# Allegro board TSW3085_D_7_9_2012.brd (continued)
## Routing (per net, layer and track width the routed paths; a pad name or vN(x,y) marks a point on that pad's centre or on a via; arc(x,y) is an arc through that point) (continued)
DA4N: length 53.3
  TOP w0.127: U1.A22 38.13,61.9
  TOP w0.152: 38.13,61.9 37.59,61.36 37.59,59.22 36.32,57.95 24.68,57.95 24.39,57.66 24.11,57.66 23.81,57.95 23.54,57.95 23.24,57.66 22.96,57.66 22.67,57.95 22.18,57.95 21.56,57.33 21.17,57.33 20.89,57.6 20.89,58.69 20.78,58.8 20.62,58.8 20.51,58.69 20.51,57.6 20.24,57.33 19.85,57.33 19.57,57.6 19.57,58.69 19.46,58.8 19.3,58.8 19.19,58.69 19.19,57.6 18.92,57.33 18.53,57.33 18.25,57.6 18.25,58.69 18.14,58.8 17.98,58.8 17.87,58.69 17.87,57.6 17.6,57.33 17.21,57.33 16.93,57.6 16.93,58.69 16.82,58.8 16.66,58.8 16.55,58.69 16.55,57.6 16.27,57.33 15.88,57.33 15.61,57.6 15.61,58.69 15.5,58.8 15.34,58.8 15.23,58.69 15.23,57.6 14.95,57.33 14.56,57.33 14.29,57.6 14.29,58.69 14.18,58.8 14.02,58.8 13.91,58.69 13.91,57.6 13.63,57.33 13.24,57.33 12.53,58.04 11.77,58.04 10.68,56.95 9.03,56.95 8.6,56.52 7.74,56.52 v1(7.29,56.06)
  BOTTOM w0.152: J13.141 6.13,55.98 6.24,56.09 6.39,56.09 6.67,56.36 6.99,56.36 v1(7.29,56.06)
DA4P: length 53.4
  TOP w0.127: 37.91,62.07 38.03,62.2 U1.B20
  TOP w0.152: v1(7.29,56.94) 7.44,56.79 8.48,56.79 8.92,57.23 10.57,57.23 11.66,58.32 12.65,58.32 13.36,57.61 13.52,57.61 13.63,57.72 13.63,58.81 13.9,59.08 14.29,59.08 14.57,58.81 14.57,57.72 14.68,57.61 14.84,57.61 14.95,57.72 14.95,58.81 15.22,59.08 15.61,59.08 15.89,58.81 15.89,57.72 16,57.61 16.16,57.61 16.27,57.72 16.27,58.81 16.55,59.08 16.93,59.08 17.21,58.81 17.21,57.72 17.32,57.61 17.48,57.61 17.59,57.72 17.59,58.81 17.87,59.08 18.26,59.08 18.53,58.81 18.53,57.72 18.64,57.61 18.8,57.61 18.91,57.72 18.91,58.81 19.19,59.08 19.58,59.08 19.85,58.81 19.85,57.72 19.96,57.61 20.12,57.61 20.23,57.72 20.23,58.81 20.51,59.08 20.9,59.08 21.17,58.81 21.17,57.72 21.28,57.61 21.44,57.61 22.07,58.23 36.21,58.23 37.31,59.34 37.31,61.48 37.91,62.07
  BOTTOM w0.152: J13.139 6.13,56.48 6.24,56.37 6.28,56.37 6.55,56.64 6.99,56.64 v1(7.29,56.94)
DA5N: length 53.3
  TOP w0.127: U1.A21 37.71,62.5
  TOP w0.152: v1(7.15,57.74) 7.4,57.99 7.99,57.99 8.57,58.57 10.87,58.57 12.14,59.84 21.66,59.84 21.81,59.69 22.09,59.69 22.24,59.84 22.52,59.84 22.67,59.69 22.95,59.69 23.11,59.84 23.39,59.84 23.54,59.69 23.82,59.69 23.97,59.84 24.36,59.84 25.3,58.9 26.64,58.9 27.39,59.65 27.39,60.65 27.5,60.76 27.66,60.76 27.77,60.65 27.77,59.2 28.05,58.93 28.44,58.93 28.71,59.2 28.71,60.65 28.82,60.76 28.98,60.76 29.09,60.65 29.09,59.2 29.37,58.93 29.76,58.93 30.03,59.2 30.03,60.65 30.14,60.76 30.3,60.76 30.41,60.65 30.41,59.2 30.69,58.93 31.08,58.93 31.35,59.2 31.35,60.65 31.46,60.76 31.62,60.76 31.73,60.65 31.73,59.2 32.01,58.93 32.4,58.93 32.67,59.2 32.67,60.65 32.79,60.76 32.94,60.76 33.05,60.65 33.05,59.2 33.33,58.93 33.72,58.93 34.08,59.28 34.08,60.34 34.82,61.09 36.3,61.09 37.71,62.5
  BOTTOM w0.152: v1(7.15,57.74) 6.85,58.04 6.55,58.04 6.39,57.89 6.39,57.74 6.13,57.48 J13.135
DA5P: length 53.4
  TOP w0.127: 37.74,62.78 37.76,62.8 U1.B19
  TOP w0.152: v1(7.15,58.62) 7.51,58.27 7.87,58.27 8.46,58.85 10.76,58.85 12.03,60.12 24.47,60.12 25.41,59.18 26.53,59.18 27.11,59.76 27.11,60.76 27.39,61.04 27.78,61.04 28.05,60.76 28.05,59.32 28.16,59.21 28.32,59.21 28.43,59.32 28.43,60.76 28.71,61.04 29.1,61.04 29.37,60.76 29.37,59.32 29.48,59.21 29.64,59.21 29.75,59.32 29.75,60.76 30.03,61.04 30.42,61.04 30.69,60.76 30.69,59.32 30.8,59.21 30.96,59.21 31.07,59.32 31.07,60.76 31.35,61.04 31.74,61.04 32.01,60.76 32.01,59.32 32.12,59.21 32.28,59.21 32.39,59.32 32.39,60.76 32.67,61.04 33.06,61.04 33.33,60.76 33.33,59.32 33.45,59.21 33.6,59.21 33.8,59.4 33.8,60.46 34.71,61.37 36.19,61.37 37.6,62.78 37.74,62.78
  BOTTOM w0.152: v1(7.15,58.62) 6.85,58.32 6.43,58.32 6.12,58 6.12,57.98 J13.133
DA6N: length 53.2
  TOP w0.127: U1.A20 38.05,63.1 38.04,63.11
  TOP w0.152: 38.04,63.11 37.22,63.11 36.35,62.23 34.87,62.23 34.38,61.75 24.91,61.75 24.77,61.61 24.77,61.01 24.46,60.71 24.03,60.71 23.72,61.01 23.72,62.08 23.57,62.23 23.37,62.23 23.22,62.08 23.22,61.01 22.91,60.71 22.48,60.71 22.17,61.01 22.17,62.08 22.02,62.23 21.82,62.23 21.67,62.08 21.67,61.01 21.36,60.71 20.93,60.71 20.62,61.01 20.62,62.08 20.47,62.23 20.27,62.23 20.12,62.08 20.12,61.01 19.81,60.71 19.38,60.71 19.07,61.01 19.07,62.08 18.92,62.23 18.72,62.23 18.57,62.08 18.57,61.01 18.26,60.71 17.83,60.71 17.52,61.01 17.52,62.08 17.37,62.23 17.17,62.23 17.02,62.08 17.02,61.01 16.72,60.71 16.28,60.71 15.97,61.01 15.97,62.08 15.82,62.23 15.62,62.23 15.47,62.08 15.47,61.01 15.17,60.71 14.73,60.71 14.42,61.01 14.42,62.08 14.28,62.23 14.07,62.23 13.41,61.57 13.08,61.57 12.86,61.34 12.58,61.34 12.35,61.57 12.07,61.57 11.84,61.34 11.56,61.34 11.33,61.57 10.9,61.57 9.14,59.82 7.45,59.82 v1(7.15,59.52)
  BOTTOM w0.152: J13.129 6.13,58.98 6.39,59.24 6.39,59.66 6.55,59.82 6.85,59.82 v1(7.15,59.52)
DA6P: length 53.3
  TOP w0.127: U1.B18 38.05,63.4 38.04,63.39
  TOP w0.152: v1(7.15,60.4) 7.45,60.1 9.03,60.1 10.78,61.85 13.29,61.85 13.95,62.51 14.39,62.51 14.7,62.2 14.7,61.13 14.84,60.99 15.05,60.99 15.2,61.13 15.2,62.2 15.5,62.51 15.94,62.51 16.25,62.2 16.25,61.13 16.39,60.99 16.6,60.99 16.74,61.13 16.74,62.2 17.05,62.51 17.49,62.51 17.8,62.2 17.8,61.13 17.94,60.99 18.15,60.99 18.29,61.13 18.29,62.2 18.6,62.51 19.04,62.51 19.35,62.2 19.35,61.13 19.49,60.99 19.7,60.99 19.84,61.13 19.84,62.2 20.15,62.51 20.59,62.51 20.9,62.2 20.9,61.13 21.04,60.99 21.25,60.99 21.39,61.13 21.39,62.2 21.7,62.51 22.14,62.51 22.45,62.2 22.45,61.13 22.59,60.99 22.8,60.99 22.94,61.13 22.94,62.2 23.25,62.51 23.69,62.51 24,62.2 24,61.13 24.14,60.99 24.35,60.99 24.49,61.13 24.49,61.72 24.8,62.03 34.27,62.03 34.75,62.51 36.23,62.51 37.11,63.39 38.04,63.39
  BOTTOM w0.152: v1(7.15,60.4) 6.85,60.1 6.43,60.1 6.12,59.78 6.12,59.48 J13.127
DA7N: length 53.2
  TOP w0.127: U1.A19 38.13,63.7 38.11,63.72
  TOP w0.152: v1(7.19,62.11) 7.49,62.41 7.98,62.41 8.69,63.12 26.12,63.12 27.39,64.39 27.55,64.39 27.66,64.28 27.66,62.78 27.94,62.51 28.33,62.51 28.6,62.78 28.6,64.28 28.71,64.39 28.87,64.39 28.98,64.28 28.98,62.78 29.26,62.51 29.65,62.51 29.92,62.78 29.92,64.28 30.03,64.39 30.19,64.39 30.3,64.28 30.3,62.78 30.58,62.51 30.97,62.51 31.24,62.78 31.24,64.28 31.35,64.39 31.51,64.39 31.62,64.28 31.62,62.78 31.9,62.51 32.29,62.51 32.56,62.78 32.56,64.28 32.68,64.39 32.83,64.39 32.95,64.28 32.95,62.78 33.22,62.51 33.61,62.51 33.88,62.78 33.88,64.28 34,64.39 34.15,64.39 34.93,63.61 36.65,63.61 36.76,63.72 38.11,63.72
  BOTTOM w0.152: J13.123 6.13,60.48 6.24,60.59 6.51,60.59 6.83,60.91 6.83,61.59 6.58,61.84 6.58,62.26 6.73,62.41 6.89,62.41 v1(7.19,62.11)
DA7P: length 53.3
  TOP w0.127: U1.B17 38.11,64 38.11,64
  TOP w0.152: 38.11,64 36.64,64 36.54,63.89 35.04,63.89 34.27,64.67 33.88,64.67 33.61,64.39 33.61,63.12 33.22,63.12 33.22,64.39 32.95,64.67 32.56,64.67 32.28,64.39 32.28,62.9 32.17,62.79 32.02,62.79 31.9,62.9 31.9,64.39 31.63,64.67 31.24,64.67 30.96,64.39 30.96,62.9 30.85,62.79 30.69,62.79 30.58,62.9 30.58,64.39 30.31,64.67 29.92,64.67 29.64,64.39 29.64,62.9 29.53,62.79 29.37,62.79 29.26,62.9 29.26,64.39 28.99,64.67 28.6,64.67 28.32,64.39 28.32,62.9 28.21,62.79 28.05,62.79 27.94,62.9 27.94,64.39 27.67,64.67 27.28,64.67 26.01,63.4 8.57,63.4 7.86,62.69 7.49,62.69 v1(7.19,62.99)
  BOTTOM w0.152: v1(7.19,62.99) 6.89,62.69 6.62,62.69 6.3,62.37 6.3,61.72 6.55,61.48 6.55,61.02 6.39,60.87 6.24,60.87 6.13,60.98 J13.121
DA8N: length 53.4
  TOP w0.127: U1.B14 37.91,65.8
  TOP w0.152: 37.91,65.8 37.87,65.76 36.12,65.76 33.17,68.71 31.48,68.71 30.95,68.17 30,68.17 29.3,68.87 29.3,69.01 29.15,69.16 28.84,69.16 28.69,69.01 28.69,68.26 28.37,67.95 27.84,67.95 27.52,68.26 27.52,69.01 27.37,69.16 27.06,69.16 26.91,69.01 26.91,68.26 26.6,67.95 26.06,67.95 25.74,68.26 25.74,69.01 25.59,69.16 25.29,69.16 25.13,69.01 25.13,68.26 24.82,67.95 24.28,67.95 23.96,68.26 23.96,69.01 23.81,69.16 23.51,69.16 23.36,69.01 23.36,68.26 23.04,67.95 22.5,67.95 22.19,68.26 22.19,69.01 22.03,69.16 21.73,69.16 21.58,69.01 21.58,68.26 21.26,67.95 20.72,67.95 20.41,68.26 20.41,69.01 20.26,69.16 19.95,69.16 19.8,69.01 19.8,68.26 19.48,67.95 18.95,67.95 18.63,68.26 18.63,69.01 18.48,69.16 18.17,69.16 18.02,69.01 18.02,68.26 17.71,67.95 17.17,67.95 16.85,68.26 16.85,69.01 16.7,69.16 16.4,69.16 16.24,69.01 16.24,68.26 15.93,67.95 15.39,67.95 15.07,68.26 15.07,69.01 14.92,69.16 14.62,69.16 14.47,69.01 14.47,68.26 14.15,67.95 13.61,67.95 13.3,68.26 13.3,68.88 13.02,69.16 11.63,69.16 11.1,68.63 7.5,68.63 v1(7.15,68.28)
  BOTTOM w0.152: J13.111 6.13,68.48 6.24,68.59 6.85,68.59 v1(7.15,68.28)
DA8P: length 53.4
  TOP w0.127: U1.A15 38.49,66.1 37.79,66.1
  TOP w0.152: 37.79,66.1 37.75,66.07 36.21,66.07 33.29,68.99 31.37,68.99 30.84,68.45 30.11,68.45 29.58,68.99 29.58,69.13 29.26,69.44 28.73,69.44 28.41,69.13 28.41,68.38 28.26,68.22 27.95,68.22 27.8,68.38 27.8,69.13 27.48,69.44 26.95,69.44 26.63,69.13 26.63,68.38 26.48,68.22 26.17,68.22 26.02,68.38 26.02,69.13 25.71,69.44 25.17,69.44 24.85,69.13 24.85,68.38 24.7,68.22 24.4,68.22 24.24,68.38 24.24,69.13 23.93,69.44 23.39,69.44 23.08,69.13 23.08,68.38 22.92,68.22 22.62,68.22 22.47,68.38 22.47,69.13 22.15,69.44 21.61,69.44 21.3,69.13 21.3,68.38 21.15,68.22 20.84,68.22 20.69,68.38 20.69,69.13 20.37,69.44 19.84,69.44 19.52,69.13 19.52,68.38 19.37,68.22 19.06,68.22 18.91,68.38 18.91,69.13 18.59,69.44 18.06,69.44 17.74,69.13 17.74,68.38 17.59,68.22 17.28,68.22 17.13,68.38 17.13,69.13 16.82,69.44 16.28,69.44 15.96,69.13 15.96,68.38 15.81,68.22 15.51,68.22 15.35,68.38 15.35,69.13 15.04,69.44 14.5,69.44 14.19,69.13 14.19,68.38 14.03,68.22 13.73,68.22 13.58,68.38 13.58,69 13.13,69.44 11.52,69.44 10.98,68.91 9.71,68.91 9.56,69.06 9.56,69.29 9.41,69.44 9.1,69.44 8.95,69.29 8.95,69.06 8.8,68.91 7.41,68.91 v1(7.15,69.17)
  BOTTOM w0.152: v1(7.15,69.17) 6.85,68.87 6.24,68.87 6.13,68.98 J13.109
DA9N: length 53.4
  TOP w0.127: U1.B13 38.58,66.4 38.57,66.39 38.23,66.39 38.22,66.38 37.4,66.38 37.39,66.37
  TOP w0.152: v1(7.15,70.13) 7.54,70.52 9.28,70.52 9.62,70.87 9.75,70.87 9.84,70.78 9.84,70.43 10.09,70.18 10.45,70.18 10.79,70.52 12.93,70.52 13.47,69.98 14.01,69.98 14.33,70.29 14.33,71.15 14.48,71.3 14.78,71.3 14.94,71.15 14.94,70.29 15.25,69.98 15.79,69.98 16.1,70.29 16.1,71.15 16.26,71.3 16.56,71.3 16.71,71.15 16.71,70.29 17.03,69.98 17.57,69.98 17.88,70.29 17.88,71.15 18.03,71.3 18.34,71.3 18.49,71.15 18.49,70.29 18.81,69.98 19.34,69.98 19.66,70.29 19.66,71.15 19.81,71.3 20.12,71.3 20.27,71.15 20.27,70.29 20.59,69.98 21.12,69.98 21.44,70.29 21.44,71.15 21.59,71.3 21.9,71.3 22.05,71.15 22.05,70.29 22.36,69.98 22.9,69.98 23.22,70.29 23.22,71.15 23.37,71.3 23.67,71.3 23.83,71.15 23.83,70.29 24.14,69.98 24.68,69.98 24.99,70.29 24.99,71.15 25.15,71.3 25.45,71.3 25.6,71.15 25.6,70.29 25.92,69.98 26.46,69.98 26.77,70.29 26.77,71.15 26.92,71.3 27.23,71.3 27.89,70.64 28.69,70.64 28.92,70.87 29.83,70.87 30.06,70.64 32.35,70.64 36.61,66.37 37.39,66.37
  BOTTOM w0.152: J13.105 6.13,69.98 6.39,70.24 6.39,70.28 6.55,70.43 6.85,70.43 v1(7.15,70.13)
DA9P: length 53.4
  TOP w0.127: 37.27,66.65 38.45,66.65 U1.A14
  TOP w0.152: 37.27,66.65 36.73,66.65 32.46,70.92 30.18,70.92 29.85,71.25 28.91,71.25 28.57,70.92 28.01,70.92 27.35,71.58 26.81,71.58 26.49,71.26 26.49,70.41 26.34,70.26 26.04,70.26 25.88,70.41 25.88,71.26 25.57,71.58 25.03,71.58 24.71,71.26 24.71,70.41 24.56,70.26 24.26,70.26 24.11,70.41 24.11,71.26 23.79,71.58 23.25,71.58 22.94,71.26 22.94,70.41 22.78,70.26 22.48,70.26 22.33,70.41 22.33,71.26 22.01,71.58 21.47,71.58 21.16,71.26 21.16,70.41 21.01,70.26 20.7,70.26 20.55,70.41 20.55,71.26 20.23,71.58 19.7,71.58 19.38,71.26 19.38,70.41 19.23,70.26 18.92,70.26 18.77,70.41 18.77,71.26 18.46,71.58 17.92,71.58 17.6,71.26 17.6,70.41 17.45,70.26 17.15,70.26 16.99,70.41 16.99,71.26 16.68,71.58 16.14,71.58 15.82,71.26 15.82,70.41 15.67,70.26 15.37,70.26 15.22,70.41 15.22,71.26 14.9,71.58 14.36,71.58 14.05,71.26 14.05,70.41 13.89,70.26 13.59,70.26 13.04,70.8 11.52,70.8 11.43,70.89 11.43,71.18 11.34,71.27 11.21,71.27 11.12,71.18 11.12,70.89 11.03,70.8 10.67,70.8 10.33,70.46 10.21,70.46 10.12,70.55 10.12,70.89 9.86,71.15 9.51,71.15 9.16,70.8 7.37,70.8 v1(7.15,71.02)
  BOTTOM w0.152: J13.103 6.13,70.48 6.16,70.45 6.43,70.71 6.85,70.71 v1(7.15,71.02)
DA10N: length 53.4
  TOP w0.127: U1.B12 38.01,67
  TOP w0.152: v1(7.15,71.81) 7.33,71.99 10.4,71.99 10.74,72.32 11.46,72.32 11.78,72.64 11.78,72.72 11.93,72.87 12.24,72.87 12.39,72.72 12.39,72.64 12.7,72.32 13.32,72.32 13.64,72.01 14.17,72.01 14.49,72.32 14.49,73.08 14.64,73.23 14.95,73.23 15.1,73.08 15.1,72.32 15.41,72.01 15.95,72.01 16.27,72.32 16.27,73.08 16.42,73.23 16.72,73.23 16.88,73.08 16.88,72.32 17.19,72.01 17.73,72.01 18.04,72.32 18.04,73.08 18.2,73.23 18.5,73.23 18.65,73.08 18.65,72.32 18.97,72.01 19.51,72.01 19.82,72.32 19.82,73.08 19.97,73.23 20.28,73.23 20.43,73.08 20.43,72.32 20.75,72.01 21.28,72.01 21.6,72.32 21.6,73.08 21.75,73.23 22.06,73.23 22.21,73.08 22.21,72.32 22.53,72.01 23.06,72.01 23.38,72.32 23.38,73.08 23.53,73.23 23.84,73.23 23.99,73.08 23.99,72.32 24.3,72.01 24.84,72.01 25.16,72.32 25.16,73.08 25.31,73.23 25.61,73.23 25.77,73.08 25.77,72.32 26.08,72.01 26.62,72.01 26.93,72.32 26.93,73.08 27.09,73.23 27.39,73.23 27.54,73.08 27.54,72.32 27.86,72.01 28.4,72.01 28.71,72.32 28.71,72.47 29.12,72.87 31.34,72.87 37.22,67 38.01,67
  BOTTOM w0.152: v1(7.15,71.81) 6.85,72.11 6.55,72.11 6.39,71.96 6.39,71.74 6.13,71.48 J13.99
DA10P: length 53.2
  TOP w0.127: U1.A13 37.99,67.3
  TOP w0.152: 37.99,67.3 37.31,67.3 31.46,73.15 29,73.15 28.43,72.58 28.43,72.44 28.28,72.29 27.98,72.29 27.82,72.44 27.82,73.19 27.51,73.51 26.97,73.51 26.65,73.19 26.65,72.44 26.5,72.29 26.2,72.29 26.05,72.44 26.05,73.19 25.73,73.51 25.19,73.51 24.88,73.19 24.88,72.44 24.72,72.29 24.42,72.29 24.27,72.44 24.27,73.19 23.95,73.51 23.41,73.51 23.1,73.19 23.1,72.44 22.95,72.29 22.64,72.29 22.49,72.44 22.49,73.19 22.17,73.51 21.64,73.51 21.32,73.19 21.32,72.44 21.17,72.29 20.86,72.29 20.71,72.44 20.71,73.19 20.4,73.51 19.86,73.51 19.54,73.19 19.54,72.44 19.39,72.29 19.09,72.29 18.93,72.44 18.93,73.19 18.62,73.51 18.08,73.51 17.76,73.19 17.76,72.44 17.61,72.29 17.31,72.29 17.16,72.44 17.16,73.19 16.84,73.51 16.3,73.51 15.99,73.19 15.99,72.44 15.83,72.29 15.53,72.29 15.38,72.44 15.38,73.19 15.06,73.51 14.52,73.51 14.21,73.19 14.21,72.44 14.06,72.29 13.75,72.29 13.44,72.6 12.82,72.6 12.67,72.76 12.67,72.84 12.35,73.15 11.82,73.15 11.5,72.84 11.5,72.76 11.35,72.6 10.63,72.6 10.29,72.27 8.85,72.27 8.7,72.42 8.7,72.57 8.55,72.72 8.24,72.72 8.09,72.57 8.09,72.42 7.94,72.27 7.58,72.27 v1(7.15,72.69)
  BOTTOM w0.152: v1(7.15,72.69) 6.85,72.39 6.43,72.39 6.12,72.07 6.12,71.98 J13.97
DA11N: length 53.3
  TOP w0.127: 37.91,67.61 37.92,67.6 37.94,67.6 ; U1.B11 38.09,67.6
  TOP w0.152: 38.09,67.6 37.94,67.6 ; v1(9.37,73.28) 9.67,73.58 11.35,73.58 11.81,74.04 11.81,74.68 12.17,75.03 12.85,75.03 13.84,74.04 14.38,74.04 14.69,74.36 14.69,75.11 14.85,75.26 15.15,75.26 15.3,75.11 15.3,74.36 15.62,74.04 16.16,74.04 16.47,74.36 16.47,75.11 16.62,75.26 16.93,75.26 17.08,75.11 17.08,74.36 17.4,74.04 17.93,74.04 18.25,74.36 18.25,75.11 18.4,75.26 18.71,75.26 18.86,75.11 18.86,74.36 19.17,74.04 19.71,74.04 20.03,74.36 20.03,75.11 20.18,75.26 20.48,75.26 20.64,75.11 20.64,74.36 20.95,74.04 21.49,74.04 21.81,74.36 21.81,75.11 21.96,75.26 22.26,75.26 22.41,75.11 22.41,74.36 22.73,74.04 23.27,74.04 23.58,74.36 23.58,75.11 23.74,75.26 24.04,75.26 24.19,75.11 24.19,74.36 24.51,74.04 25.05,74.04 25.36,74.36 25.36,75.11 25.51,75.26 25.82,75.26 25.97,75.11 25.97,74.36 26.29,74.04 26.82,74.04 27.14,74.36 27.14,75.11 27.29,75.26 27.6,75.26 27.75,75.11 27.75,74.97 28.06,74.65 30.89,74.65 37.91,67.61
  BOTTOM w0.152: J13.93 6.13,72.98 6.24,73.09 6.8,73.09 7.32,73.61 9.05,73.61 v1(9.37,73.28)
DA11P: length 53.3
  TOP w0.152: U1.A12 38.48,67.88 38.06,67.88 31,74.93 28.18,74.93 28.03,75.08 28.03,75.22 27.71,75.54 27.18,75.54 26.86,75.22 26.86,74.47 26.71,74.32 26.4,74.32 26.25,74.47 26.25,75.22 25.93,75.54 25.4,75.54 25.08,75.22 25.08,74.47 24.93,74.32 24.62,74.32 24.47,74.47 24.47,75.22 24.16,75.54 23.62,75.54 23.3,75.22 23.3,74.47 23.15,74.32 22.85,74.32 22.69,74.47 22.69,75.22 22.38,75.54 21.84,75.54 21.53,75.22 21.53,74.47 21.37,74.32 21.07,74.32 20.92,74.47 20.92,75.22 20.6,75.54 20.06,75.54 19.75,75.22 19.75,74.47 19.6,74.32 19.29,74.32 19.14,74.47 19.14,75.22 18.82,75.54 18.29,75.54 17.97,75.22 17.97,74.47 17.82,74.32 17.51,74.32 17.36,74.47 17.36,75.22 17.04,75.54 16.51,75.54 16.19,75.22 16.19,74.47 16.04,74.32 15.73,74.32 15.58,74.47 15.58,75.22 15.27,75.54 14.73,75.54 14.41,75.22 14.41,74.47 14.26,74.32 13.96,74.32 12.97,75.31 12.05,75.31 11.53,74.79 11.53,74.16 11.24,73.86 10.54,73.86 10.45,73.95 10.45,74.21 10.36,74.3 10.24,74.3 10.15,74.21 10.15,73.95 10.06,73.86 9.67,73.86 v1(9.37,74.16)
  BOTTOM w0.152: J13.91 6.13,73.48 6.24,73.37 6.68,73.37 7.2,73.89 9.16,73.89 9.37,74.1 v1(9.37,74.16)
DA12N: length 53.3
  TOP w0.127: U1.A11 39.84,69.24 39.84,69.49 39.83,69.5
  TOP w0.152: 39.83,69.5 39.23,70.1 37.08,70.1 34.03,73.16 33.9,73.16 33.77,73.16 33.56,73.38 33.56,73.5 33.56,73.63 33.34,73.84 33.22,73.84 33.09,73.84 32.87,74.06 32.87,74.19 32.87,74.31 32.66,74.53 32.53,74.53 32.41,74.53 32.19,74.75 32.19,74.87 32.19,75 30.61,76.58 29.62,76.58 29.29,76.91 28.98,76.91 28.83,76.76 28.83,76.2 28.57,75.95 27.79,75.95 27.66,76.07 27.66,76.76 27.51,76.91 27.2,76.91 27.05,76.76 27.05,76.2 26.8,75.95 26.01,75.95 25.88,76.07 25.88,76.76 25.73,76.91 25.42,76.91 25.27,76.76 25.27,76.2 25.02,75.95 24.23,75.95 24.1,76.07 24.1,76.76 23.95,76.91 23.65,76.91 23.49,76.76 23.49,76.2 23.24,75.95 22.45,75.95 22.33,76.07 22.33,76.76 22.17,76.91 21.87,76.91 21.72,76.76 21.72,76.26 21.4,75.95 20.86,75.95 20.55,76.26 20.55,76.76 20.4,76.91 20.09,76.91 19.94,76.76 19.94,76.26 19.62,75.95 19.09,75.95 18.77,76.26 18.77,76.76 18.62,76.91 18.31,76.91 18.16,76.76 18.16,76.26 17.84,75.95 17.31,75.95 16.99,76.26 16.99,76.76 16.84,76.91 16.53,76.91 16.38,76.76 16.38,76.26 16.07,75.95 15.53,75.95 15.21,76.26 15.21,76.76 15.06,76.91 14.76,76.91 14.6,76.76 14.6,76.26 14.29,75.95 13.75,75.95 13.44,76.26 13.44,76.76 13.28,76.91 12.98,76.91 12.83,76.76 12.83,76.26 12.51,75.95 11.97,75.95 11.81,76.11 10.85,76.11 10.66,75.92 9.19,75.92 8.66,75.39 7.86,75.39 v1(7.15,74.68)
  BOTTOM w0.152: v1(7.15,74.68) 6.85,74.98 6.55,74.98 6.39,74.83 6.39,74.74 6.13,74.48 J13.87
DA12P: length 53.4
  TOP w0.127: U1.B10 40.1,69.63
  TOP w0.152: 40.1,69.63 39.34,70.38 37.2,70.38 30.72,76.86 29.73,76.86 29.4,77.19 28.86,77.19 28.55,76.87 28.55,76.32 28.46,76.23 27.94,76.23 27.94,76.87 27.62,77.19 27.09,77.19 26.77,76.87 26.77,76.31 26.68,76.23 26.16,76.23 26.16,76.87 25.85,77.19 25.31,77.19 24.99,76.87 24.99,76.31 24.9,76.23 24.38,76.23 24.38,76.87 24.07,77.19 23.53,77.19 23.21,76.87 23.21,76.31 23.13,76.23 22.6,76.23 22.6,76.87 22.29,77.19 21.75,77.19 21.44,76.87 21.44,76.38 21.28,76.23 20.98,76.23 20.83,76.38 20.83,76.87 20.51,77.19 19.97,77.19 19.66,76.87 19.66,76.38 19.51,76.23 19.2,76.23 19.05,76.38 19.05,76.87 18.73,77.19 18.2,77.19 17.88,76.87 17.88,76.38 17.73,76.23 17.42,76.23 17.27,76.38 17.27,76.87 16.96,77.19 16.42,77.19 16.1,76.87 16.1,76.38 15.95,76.23 15.65,76.23 15.49,76.38 15.49,76.87 15.18,77.19 14.64,77.19 14.32,76.87 14.32,76.38 14.17,76.23 13.87,76.23 13.71,76.38 13.71,76.87 13.4,77.19 12.86,77.19 12.55,76.87 12.55,76.38 12.39,76.23 12.09,76.23 11.93,76.39 10.73,76.39 10.54,76.2 9.08,76.2 8.55,75.67 7.75,75.67 7.64,75.57 7.61,75.57 7.61,75.56 v1(7.15,75.56)
  BOTTOM w0.152: v1(7.15,75.56) 6.85,75.26 6.43,75.26 6.14,74.97 6.13,74.98 J13.85
DA13N: length 53.2
  TOP w0.127: U1.A10 40.41,69.21
  TOP w0.152: 40.41,69.21 40.41,69.25 40.4,69.27 40.4,69.31 40.39,69.33 40.39,69.94 40.13,70.19 40.13,70.19 39.08,71.25 37.47,71.25 33.84,74.87 33.46,74.87 33.25,75.08 33.25,75.46 33.03,75.68 32.65,75.68 32.44,75.9 32.44,76.28 32.22,76.49 31.84,76.49 31.62,76.71 31.62,77.09 30.86,77.85 28.7,77.85 28.54,78.01 28.54,78.54 28.39,78.69 28.08,78.69 27.93,78.54 27.93,77.97 27.69,77.72 27.08,77.72 26.76,78.04 26.76,78.54 26.61,78.69 26.3,78.69 26.15,78.54 26.15,78.04 25.84,77.72 25.3,77.72 24.98,78.04 24.98,78.54 24.83,78.69 24.53,78.69 24.37,78.54 24.37,78.04 24.06,77.72 23.52,77.72 23.2,78.04 23.2,78.54 23.05,78.69 22.75,78.69 22.6,78.54 22.6,78.04 22.28,77.72 21.74,77.72 21.43,78.04 21.43,78.54 21.27,78.69 20.97,78.69 20.82,78.54 20.82,78.04 20.5,77.72 19.96,77.72 19.65,78.04 19.65,78.54 19.5,78.69 19.19,78.69 19.04,78.54 19.04,78.04 18.72,77.72 18.19,77.72 17.87,78.04 17.87,78.54 17.72,78.69 17.41,78.69 17.26,78.54 17.26,78.04 16.95,77.72 16.41,77.72 16.09,78.04 16.09,78.54 15.94,78.69 15.64,78.69 15.48,78.54 15.48,78.04 15.17,77.72 14.63,77.72 14.31,78.04 14.31,78.36 14.19,78.49 13.71,78.49 13.71,78.04 13.39,77.72 10.8,77.72 9.83,76.76 7.45,76.76 v1(7.15,76.46)
  BOTTOM w0.152: v1(7.15,76.46) 6.85,76.76 6.55,76.76 6.39,76.61 6.39,76.24 6.13,75.98 J13.81
DA13P: length 53.4
  TOP w0.127: U1.B9 40.69,68.55 40.69,68.91 40.7,68.92 40.7,69.47 40.67,69.51
  TOP w0.152: 40.67,69.51 40.67,70.05 40.41,70.31 40.41,70.31 39.19,71.53 37.58,71.53 30.98,78.13 28.82,78.13 28.82,78.65 28.5,78.97 27.97,78.97 27.65,78.65 27.65,78.08 27.57,78 27.19,78 27.04,78.16 27.04,78.65 26.72,78.97 26.19,78.97 25.87,78.65 25.87,78.16 25.72,78 25.41,78 25.26,78.16 25.26,78.65 24.95,78.97 24.41,78.97 24.09,78.65 24.09,78.16 23.94,78 23.64,78 23.48,78.16 23.48,78.65 23.17,78.97 22.63,78.97 22.32,78.65 22.32,78.16 22.16,78 21.86,78 21.71,78.16 21.71,78.65 21.39,78.97 20.85,78.97 20.54,78.65 20.54,78.16 20.39,78 20.08,78 19.93,78.16 19.93,78.65 19.61,78.97 19.08,78.97 18.76,78.65 18.76,78.16 18.61,78 18.3,78 18.15,78.16 18.15,78.65 17.83,78.97 17.3,78.97 16.98,78.65 16.98,78.16 16.83,78 16.52,78 16.37,78.16 16.37,78.65 16.06,78.97 15.52,78.97 15.2,78.65 15.2,78.16 15.05,78 14.75,78 14.59,78.16 14.59,78.49 14.58,78.49 14.3,78.77 13.59,78.77 13.43,78.6 13.43,78.35 13.08,78 10.68,78 9.71,77.04 7.45,77.04 v1(7.15,77.34)
  BOTTOM w0.152: J13.79 6.12,76.48 6.12,76.72 6.43,77.04 6.85,77.04 v1(7.15,77.34)
DA14N: length 53.3
  TOP w0.127: 41.27,69.7 41.29,69.68 41.29,69.47 41.29,69.47 41.29,68.55 U1.B8
  TOP w0.152: 41.27,69.7 41.27,70.66 41.23,70.71 41.23,71.88 40.69,72.42 37.63,72.42 35.28,74.76 35.28,75.32 30.24,80.37 29.76,80.37 29.67,80.28 29.67,79.92 29.25,79.5 28.57,79.5 28.26,79.82 28.26,80.11 28.1,80.26 27.8,80.26 27.65,80.11 27.65,79.82 27.33,79.5 26.79,79.5 26.48,79.82 26.48,80.11 26.32,80.26 26.02,80.26 25.87,80.11 25.87,79.82 25.55,79.5 25.02,79.5 24.7,79.82 24.7,80.11 24.55,80.26 24.24,80.26 24.09,80.11 24.09,79.82 23.77,79.5 23.24,79.5 22.92,79.82 22.92,80.11 22.77,80.26 22.46,80.26 22.31,80.11 22.31,79.82 22,79.5 21.46,79.5 21.14,79.82 21.14,80.11 20.99,80.26 20.69,80.26 20.53,80.11 20.53,79.82 20.22,79.5 19.68,79.5 19.37,79.82 19.37,80.11 19.21,80.26 18.91,80.26 18.76,80.11 18.76,79.82 18.44,79.5 17.9,79.5 17.59,79.82 17.59,80.11 17.43,80.26 17.13,80.26 16.98,80.11 16.98,79.82 16.66,79.5 16.13,79.5 15.81,79.82 15.81,80.11 15.66,80.26 15.35,80.26 15.2,80.11 15.2,79.82 14.88,79.5 13.33,79.5 13.24,79.41 13.24,79.4 12.98,79.15 12.63,79.15 12.37,79.4 12.37,79.77 12.28,79.86 12.16,79.86 12.07,79.77 12.07,79.75 11.82,79.5 11.18,79.5 9.68,78 6.8,78 v1(6.5,77.7)
  BOTTOM w0.152: J13.75 6.28,77.48 v1(6.5,77.7)
DA14P: length 53.3
  TOP w0.127: U1.A8 41.55,69.24 41.55,69.81
  TOP w0.152: v1(6.5,78.58) 6.8,78.28 9.56,78.28 11.06,79.78 11.7,79.78 11.79,79.87 11.79,79.88 12.04,80.14 12.4,80.14 12.65,79.88 12.65,79.51 12.74,79.43 12.87,79.43 12.96,79.51 12.96,79.53 13.21,79.78 14.77,79.78 14.92,79.93 14.92,80.23 15.24,80.54 15.77,80.54 16.09,80.23 16.09,79.93 16.24,79.78 16.55,79.78 16.7,79.93 16.7,80.23 17.01,80.54 17.55,80.54 17.87,80.23 17.87,79.93 18.02,79.78 18.32,79.78 18.48,79.93 18.48,80.23 18.79,80.54 19.33,80.54 19.64,80.23 19.64,79.93 19.8,79.78 20.1,79.78 20.25,79.93 20.25,80.23 20.57,80.54 21.11,80.54 21.42,80.23 21.42,79.93 21.58,79.78 21.88,79.78 22.03,79.93 22.03,80.23 22.35,80.54 22.88,80.54 23.2,80.23 23.2,79.93 23.35,79.78 23.66,79.78 23.81,79.93 23.81,80.23 24.13,80.54 24.66,80.54 24.98,80.23 24.98,79.93 25.13,79.78 25.44,79.78 25.59,79.93 25.59,80.23 25.9,80.54 26.44,80.54 26.76,80.23 26.76,79.93 26.91,79.78 27.21,79.78 27.37,79.93 27.37,80.23 27.68,80.54 28.22,80.54 28.53,80.23 28.53,79.93 28.69,79.78 29.13,79.78 29.39,80.04 29.39,80.39 29.64,80.65 30.35,80.65 35.56,75.44 35.56,74.88 37.74,72.69 40.81,72.69 41.51,71.99 41.51,70.83 41.55,70.78 41.55,69.81
  BOTTOM w0.152: v1(6.5,78.58) 5.9,77.98 J13.73
DA15N: length 53.2
  TOP w0.127: U1.B7 41.9,69.53 41.91,69.54 41.91,69.91 41.9,69.92 41.9,69.96
  TOP w0.152: 41.9,69.96 41.9,70.2 41.83,70.27 41.83,70.86 41.88,70.91 41.88,72.2 40.47,73.61 38.91,73.61 37.62,74.9 37.61,74.9 30.62,81.89 30.15,81.89 29.41,81.15 28.88,81.15 28.56,81.47 28.56,81.71 28.41,81.86 28.1,81.86 27.95,81.71 27.95,81.47 27.64,81.15 27.1,81.15 26.78,81.47 26.78,81.71 26.63,81.86 26.33,81.86 26.17,81.71 26.17,81.47 25.86,81.15 25.32,81.15 25.01,81.47 25.01,81.71 24.85,81.86 24.55,81.86 24.4,81.71 24.4,81.47 24.08,81.15 23.54,81.15 23.23,81.47 23.23,81.71 23.08,81.86 22.77,81.86 22.62,81.71 22.62,81.47 22.3,81.15 21.77,81.15 21.45,81.47 21.45,81.71 21.3,81.86 20.99,81.86 20.84,81.71 20.84,81.47 20.52,81.15 19.99,81.15 19.67,81.47 19.67,81.71 19.52,81.86 19.21,81.86 19.06,81.71 19.06,81.47 18.75,81.15 18.21,81.15 17.89,81.47 17.89,81.71 17.74,81.86 17.44,81.86 17.28,81.71 17.28,81.47 16.97,81.15 16.43,81.15 16.12,81.47 16.12,81.71 15.96,81.86 15.66,81.86 15.51,81.71 15.51,81.47 15.19,81.15 14.65,81.15 13.94,81.86 12.26,81.86 11.55,81.15 10.16,81.15 8.76,79.76 7.92,79.76 7.61,79.45 7.19,79.45 v1(6.89,79.15)
  BOTTOM w0.152: v1(6.89,79.15) 6.84,79.09 6.24,79.09 6.13,78.98 J13.69
DA15P: length 53.4
  TOP w0.127: U1.A7 42.16,69.23 42.16,69.91 42.18,69.92 42.18,69.96
  TOP w0.152: 42.18,69.96 42.18,70.32 42.11,70.38 42.11,70.74 42.16,70.79 42.16,72.31 40.59,73.89 39.03,73.89 37.74,75.18 37.72,75.18 30.73,82.17 30.04,82.17 29.3,81.43 28.99,81.43 28.84,81.58 28.84,81.83 28.53,82.14 27.99,82.14 27.67,81.83 27.67,81.58 27.52,81.43 27.22,81.43 27.06,81.58 27.06,81.83 26.75,82.14 26.21,82.14 25.9,81.83 25.9,81.58 25.74,81.43 25.44,81.43 25.29,81.58 25.29,81.83 24.97,82.14 24.43,82.14 24.12,81.83 24.12,81.58 23.96,81.43 23.66,81.43 23.51,81.58 23.51,81.83 23.19,82.14 22.66,82.14 22.34,81.83 22.34,81.58 22.19,81.43 21.88,81.43 21.73,81.58 21.73,81.83 21.41,82.14 20.88,82.14 20.56,81.83 20.56,81.58 20.41,81.43 20.1,81.43 19.95,81.58 19.95,81.83 19.64,82.14 19.1,82.14 18.78,81.83 18.78,81.58 18.63,81.43 18.33,81.43 18.17,81.58 18.17,81.83 17.86,82.14 17.32,82.14 17.01,81.83 17.01,81.58 16.85,81.43 16.55,81.43 16.4,81.58 16.4,81.83 16.08,82.14 15.54,82.14 15.23,81.83 15.23,81.58 15.07,81.43 14.77,81.43 14.06,82.14 12.14,82.14 11.43,81.43 10.04,81.43 8.65,80.04 7.8,80.04 7.5,79.73 7.19,79.73 v1(6.89,80.03)
  BOTTOM w0.152: J13.67 6.13,79.48 6.24,79.37 6.39,79.37 6.89,79.87 v1(6.89,80.03)
DAC_ALARM_SDO: length 66.3
  BOTTOM w0.102: 48.46,69.67 48.26,69.67 45.5,66.91 45.13,66.91 44.82,66.6 44.82,66.23 44.5,65.91 44.07,65.91 43.81,65.66 43.81,62.99 43.78,62.96 43.78,62.2 43.7,62.11 v5(43.7,61.25)
  BOTTOM w0.152: U4.10 85.32,99.42 84.3,98.4 81.76,98.4 69.25,85.88 69.25,83.85 64.52,79.12 56.39,79.12 55.37,78.1 55.37,71.63 53.98,70.23 49.02,70.23 48.46,69.67
DAC_FIFO_OSTR: length 7
  TOP w0.152: C2.2 47.65,74.4 47.65,73.81 R5.2 46.99,73.15 46.99,71.55 46.84,71.4 46.84,70.74 46.35,70.26 45.66,70.26 45.2,69.8 U1.A2
DAC_FIFO_OSTRC: length 7
  TOP w0.127: U1.B2 44.9,69.85
  TOP w0.152: 44.9,69.85 44.9,69.86 46.71,71.67 46.71,73.18 R5.1 C1.2
DAC_GPIO_0: length 101.2
  L3_PWR w0.152: v1(3.94,88.98) 3.97,88.95 6.1,88.95 6.11,88.96 6.51,88.96 6.52,88.95 6.93,88.95 8,87.88 10.92,87.88 11.94,86.87 13.08,86.87 14.61,88.39 14.61,88.42 35.36,109.17 39.9,109.17 42.14,106.93 42.9,106.93 43.05,107.09 47.83,107.09 47.98,106.93 48.47,106.93 48.69,106.71 49.1,106.71 49.2,106.81 49.83,106.81 50.06,106.58 51.18,106.58 51.94,107.34 76.81,107.34 82.83,101.32 88.55,101.32 v1(89.32,100.55)
  BOTTOM w0.152: J13.49 v1(3.94,88.98)
DAC_GPIO_1: length 100.1
  L3_PWR w0.152: v1(88.52,100.55) 88.4,100.55 87.92,101.03 84.32,101.03 84.25,100.97 82.17,100.97 76.15,106.98 57.2,106.98 55.69,105.47 52.93,105.47 51.64,104.18 51.64,103.12 45.52,97 45.52,95.25 35.99,85.73 12.19,85.73 10.41,87.5 7.03,87.5 6.55,87.99 4.45,87.99 v1(3.94,87.48)
  BOTTOM w0.152: J13.55 v1(3.94,87.48)
DAC_GPIO_2: length 100.7
  L3_PWR w0.152: v1(3.28,86.98) 10.05,86.98 12.83,84.2 35.18,84.2 46.02,95.04 46.02,96.8 52.02,102.8 52.02,104.09 52.99,105.06 55.78,105.06 57.35,106.63 74.22,106.63 80.78,100.06 86.44,100.06 v1(86.92,100.55)
  BOTTOM w0.152: J13.57 v1(3.28,86.98)
DAC_RESET: length 32.2
  TOP w0.102: 45.34,59.23 45.34,59.31 45.5,59.47 45.5,59.59 45.62,59.71 45.62,59.92 45.5,60.04 45.5,60.47 45.5,60.47 45.5,60.72 45.5,60.73 v5(45.5,61.25)
  TOP w0.152: 45.34,59.23 45.34,58.42 45.15,58.23 45.15,57.26 45.15,57.25 45.15,56.79 45.09,56.72 45.09,53.34 45.97,52.45 45.97,40.77 46.94,39.8 v1(46.94,37.53) 47,37.59 SW1.2
  BOTTOM w0.152: v1(46.94,37.53) 46.04,37.53 R46.1 C47.1 R7.1
DAC_RST: length 98.4
  BOTTOM w0.152: J13.48 10.1,89.48 9.53,88.9 9.53,88.27 8.89,87.63 7.62,87.63 6.98,87 6.98,85.73 6.35,85.09 5.08,85.09 3.18,83.19 3.18,52.81 2.73,52.37 2.73,51.08 2.95,50.87 2.95,50.22 3.18,49.99 3.18,43.81 4.45,42.55 33.78,42.55 33.81,42.52 37.87,42.52 41.53,38.86 41.53,35.96 41.8,35.69 R7.2
DAC_SPI_EN: length 76
  TOP w0.152: v1(86.12,111.8) 85.32,111 85.32,107.54 84.66,106.88 77.8,106.88 v1(73.49,102.58)
  BOTTOM w0.102: v5(44.3,61.25) 43.89,60.83 43.43,60.83 43.05,61.21 43.05,61.96 42.8,62.21 42.8,62.32 42.8,62.33 42.8,65.58 42.5,65.88 42.07,65.88 41.78,66.17 41.78,67.2 41.78,67.2 41.78,68.01 41.55,68.23 41.55,70.54
  BOTTOM w0.152: v1(73.49,102.58) 45.09,74.17 44.58,74.17 42.67,72.26 42.42,72.26 41.91,71.76 41.91,71.5 41.55,71.15 41.55,70.54
DACCLK: length 27.5
  TOP w0.152: 44.88,99.64 44.7,99.47 44.58,99.47 44.15,99.03 44.15,98.02 43.62,97.49 R51.1 43.12,96.97 42.75,96.6 42.75,96.45 42.79,96.41 42.79,96.26 42.68,96.15 42.53,96.15 42.49,96.19 42.34,96.19 41.4,95.25 41.4,88 44.6,84.8 44.6,76.05 C4.2
DACCLKC: length 27.5
  TOP w0.152: U16.15 44.32,99.79 44.32,99.7 43.8,99.17 43.8,98.16 43.44,97.8 42.95,97.8 R52.1 42.87,97.21 41.06,95.4 41.06,87.94 44.32,84.68 44.32,76.07 C3.2
DATACLK-N: length 18
  TOP w0.152: SJP8.2 15.52,64.97 15.49,65 15.14,65 15.04,64.9 14.91,64.9 14.89,64.87 13.84,64.87 12.94,63.97 12.36,63.97 12.05,64.28 12.05,65.86 11.91,66 11.7,66 11.56,65.86 11.56,64.57 11.09,64.1 10.09,64.1 9.63,64.57 9.63,66.68 9.02,67.28 v1(9.02,67.3)
  BOTTOM w0.152: J13.117 6.13,66.97 6.24,67.09 7.16,67.09 7.61,67.54 8.78,67.54 v1(9.02,67.3)
DATACLK-P: length 17.8
  TOP w0.152: SJP7.2 15.06,65.3 14.68,65.3 14.53,65.46 14.3,65.46 14,65.15 13.73,65.15 12.83,64.25 12.48,64.25 12.33,64.39 12.33,64.62 12.57,64.86 12.57,65.48 12.33,65.72 12.33,65.97 12.02,66.28 11.59,66.28 11.28,65.97 11.28,64.68 10.97,64.38 10.21,64.38 9.91,64.68 9.91,64.85 10.21,65.15 10.21,65.35 9.91,65.66 9.91,65.94 10.13,66.17 10.13,66.4 9.91,66.62 9.91,66.8 9.53,67.18 9.53,67.44 9.23,67.73 9.23,67.74 v1(9.02,67.96)
  BOTTOM w0.152: J13.115 6.13,67.48 6.24,67.36 7.04,67.36 7.49,67.82 8.88,67.82 v1(9.02,67.96)
DATACLKN: length 25.9
  TOP w0.127: 37.38,65.19 37.41,65.19 37.42,65.2 U1.B15
  TOP w0.152: SJP1.2 23.6,65.15 23.79,65.34 24.07,65.34 24.23,65.51 24.23,65.79 24.37,65.93 24.78,65.93 24.88,66.03 24.88,66.43 24.99,66.55 25.54,66.55 26.07,66.01 26.51,66.01 26.82,66.32 26.82,66.96 26.96,67.11 27.17,67.11 27.31,66.96 27.31,66.32 27.62,66.01 28.06,66.01 28.37,66.32 28.37,66.96 28.51,67.11 28.72,67.11 28.86,66.96 28.86,66.32 29.17,66.01 29.61,66.01 29.91,66.32 29.91,66.96 30.06,67.11 30.27,67.11 30.41,66.96 30.41,66.32 30.72,66.01 31.16,66.01 31.46,66.32 31.46,66.96 31.61,67.11 31.81,67.11 31.96,66.96 31.96,66.32 32.27,66.01 32.71,66.01 33.01,66.32 33.01,66.96 33.16,67.11 33.36,67.11 33.51,66.96 33.51,66.32 33.82,66.01 34.81,66.01 35.63,65.19 35.88,65.19 36.07,65 36.56,65 36.75,65.19 37.38,65.19
DATACLKP: length 25.9
  TOP w0.127: 37.38,65.47 37.41,65.47 37.43,65.46 37.88,65.46 37.92,65.5 U1.A16
  TOP w0.152: 37.38,65.47 35.75,65.47 34.92,66.29 33.93,66.29 33.79,66.44 33.79,67.08 33.48,67.39 33.04,67.39 32.73,67.08 32.73,66.44 32.59,66.29 32.38,66.29 32.24,66.44 32.24,67.08 31.93,67.39 31.49,67.39 31.18,67.08 31.18,66.44 31.04,66.29 30.83,66.29 30.69,66.44 30.69,67.08 30.38,67.39 29.94,67.39 29.64,67.08 29.64,66.44 29.49,66.29 29.29,66.29 29.14,66.44 29.14,67.08 28.83,67.39 28.39,67.39 28.09,67.08 28.09,66.44 27.94,66.29 27.74,66.29 27.59,66.44 27.59,67.08 27.28,67.39 26.85,67.39 26.54,67.08 26.54,66.44 26.39,66.29 26.19,66.29 25.65,66.83 24.88,66.83 23.71,65.66 SJP6.2
DCLK-N: length 59.5
  TOP w0.152: 23.24,66.17 23.24,66.21 v1(22.81,66.64) ; SJP8.1 v1(16.51,66.54)
  BOTTOM w0.152: v1(22.81,66.64) 22.06,66.64 21.88,66.46 21.25,66.46 20.93,66.78 20.93,68.1 21.25,68.41 23.44,68.41 23.65,68.62 23.65,69.89 23.96,70.21 25.37,70.21 25.53,70.36 25.53,71.1 25.37,71.25 22.08,71.25 21.69,71.64 21.69,72.31 22.66,73.28 22.66,73.71 22.15,74.22 19.99,74.22 19.68,73.91 19.68,71.8 18.62,70.74 18.62,70 18.77,69.85 19.83,69.85 20.14,69.54 20.14,68.57 19.83,68.25 18.77,68.25 18.62,68.1 18.62,67.36 18.77,67.21 19.83,67.21 20.14,66.89 20.14,65.93 19.83,65.61 18.77,65.61 18.62,65.46 18.62,64.72 18.77,64.57 19.83,64.57 20.14,64.25 20.14,63.28 19.83,62.97 18.77,62.97 18.62,62.82 18.62,61.85 18.13,61.36 15.1,61.36 14.78,61.68 14.78,62.65 15.1,62.96 17.29,62.96 17.44,63.11 17.44,63.85 17.29,64 15.1,64 14.78,64.32 14.78,65.29 15.1,65.6 17.29,65.6 17.44,65.76 17.44,66.97 17.29,67.12 16.81,67.12 16.51,66.81 v1(16.51,66.54)
DCLK-P: length 59.6
  TOP w0.152: v1(22,67.25) 22,67.01 21.97,66.98 SJP6.1 ; SJP7.1 15.24,66.51 v1(15.77,67.04)
  BOTTOM w0.152: v1(22,67.25) 22,66.97 21.77,66.74 21.36,66.74 21.21,66.89 21.21,67.98 21.36,68.14 23.56,68.14 23.93,68.5 23.93,69.77 24.08,69.93 25.49,69.93 25.81,70.24 25.81,71.21 25.49,71.53 22.2,71.53 21.97,71.76 21.97,72.2 22.94,73.16 22.94,73.83 22.26,74.5 19.87,74.5 19.4,74.02 19.4,71.92 18.34,70.86 18.34,69.89 18.65,69.57 19.71,69.57 19.86,69.42 19.86,68.68 19.71,68.53 18.65,68.53 18.34,68.21 18.34,67.25 18.65,66.93 19.71,66.93 19.86,66.78 19.86,66.04 19.71,65.89 18.65,65.89 18.34,65.57 18.34,64.6 18.65,64.29 19.71,64.29 19.86,64.14 19.86,63.4 19.71,63.25 18.65,63.25 18.34,62.93 18.34,61.96 18.02,61.64 15.21,61.64 15.06,61.79 15.06,62.53 15.21,62.68 17.41,62.68 17.72,63 17.72,63.97 17.41,64.28 15.21,64.28 15.06,64.43 15.06,65.17 15.21,65.32 17.41,65.32 17.72,65.64 17.72,67.08 17.41,67.4 16.7,67.4 16.34,67.04 v1(15.77,67.04)
DCLKN: length 8.7
  TOP w0.152: SJP8.3 16.73,64.17 18.25,64.17 18.56,64.49 18.56,65.24 18.71,65.39 19.02,65.39 19.17,65.24 19.17,64.49 19.49,64.17 23.2,64.17 SJP1.3
DCLKP: length 8.8
  TOP w0.152: SJP7.3 15.35,64.35 16.06,64.35 16.16,64.45 18.13,64.45 18.28,64.6 18.28,65.36 18.6,65.67 19.13,65.67 19.45,65.36 19.45,64.6 19.6,64.45 21.77,64.45 21.96,64.64 SJP6.3
EXTIO: length 4
  TOP w0.102: 48.46,60.25 48.01,60.71 48.01,61.09 47.15,61.95 U1.A34
  TOP w0.152: 48.46,60.25 49.02,59.69 49.02,59.56 C337.1
FIFO_ISTRN: length 53.2
  TOP w0.127: 37.96,64.3 37.96,64.3 U1.A18
  TOP w0.152: v2(25.91,64.39) 25.91,64.72 26.29,65.1 34.62,65.1 35.36,64.36 37.28,64.36 37.34,64.3 37.57,64.3 37.96,64.3
  BOTTOM w0.152: v2(25.91,64.39) 25.71,64.19 25.34,64.19 24.54,63.38 24.54,53.91 24.87,53.58 24.87,52.97 24.54,52.64 24.54,52.03 24.87,51.7 24.87,51.09 24.54,50.76 24.54,50.01 21.61,47.08 19.88,47.08 19.73,46.93 19.73,46.02 19.41,45.7 18.87,45.7 18.56,46.02 18.56,48.31 18.41,48.46 18.1,48.46 17.95,48.31 17.95,46.02 17.63,45.7 17.1,45.7 16.78,46.02 16.78,48.31 16.63,48.46 16.32,48.46 16.17,48.31 16.17,47.4 15.85,47.08 12.41,47.08 12.3,46.97 J13.178
FIFO_ISTRP: length 53.3
  TOP w0.127: 37.96,64.58 37.98,64.6 U1.B16
  TOP w0.152: v2(25.45,64.87) 25.51,64.93 25.73,64.93 26.17,65.38 34.74,65.38 35.48,64.64 37.39,64.64 37.45,64.58 37.96,64.58
  BOTTOM w0.152: v2(25.45,64.87) 25.15,64.57 25.15,64.39 24.26,63.5 24.26,50.13 21.49,47.36 19.76,47.36 19.45,47.05 19.45,46.13 19.29,45.98 18.99,45.98 18.84,46.13 18.84,48.43 18.52,48.74 17.98,48.74 17.67,48.43 17.67,46.13 17.52,45.98 17.21,45.98 17.06,46.13 17.06,48.43 16.74,48.74 16.21,48.74 15.89,48.43 15.89,47.51 15.74,47.36 12.41,47.36 12.3,47.47 J13.176
FIFO_OSTR: length 28.6
  TOP w0.152: C2.1 46.99,76.07 46.99,80.54 50.33,83.88 50.33,95.44 48.42,97.35 R92.1 47.91,97.82 47.28,98.45 47.28,98.78 47.78,99.27 47.78,99.93 47.29,100.41 47.29,100.52 U16.20
FIFO_OSTRC: length 28.6
  TOP w0.152: U16.19 46.96,100.15 47.07,100.15 47.43,99.78 47.43,99.42 46.94,98.92 46.94,98.31 47.69,97.56 R60.1 48.19,97.1 48.63,96.65 48.63,96.5 48.58,96.45 48.58,96.3 48.69,96.19 48.84,96.19 48.9,96.24 49.05,96.24 49.99,95.3 49.99,84.02 46.74,80.77 46.74,80.68 46.71,80.66 46.71,76.05 C1.1
FPGA_CLKOUTN: length 63
  BOTTOM w0.152: J13.118 12.3,66.97 12.41,67.09 13.46,67.09 15.52,69.14 15.52,90.94 21.87,97.29 21.87,100.48 29.76,108.37 29.99,108.37 30.42,108.8 30.42,109.03 30.85,109.46 31.08,109.46 31.51,109.89 31.51,110.12 35.41,114.02 39,114.02 39.41,113.62 v1(39.41,113.2)
FPGA_CLKOUTP: length 63.1
  BOTTOM w0.152: v1(40.14,113.93) 39.48,113.93 39.12,114.3 35.29,114.3 21.59,100.6 21.59,97.41 15.24,91.06 15.24,69.26 13.35,67.36 12.41,67.36 12.3,67.48 J13.116
GAIN_SEL: length 56.8
  L6_PWR w0.152: v1(87.22,60.78) 86.49,61.52 86.49,75.18 85.47,76.2 85.47,82.04 86.55,83.12 86.55,91.27 85.39,92.43 85.39,98.4 83.52,100.28 83.52,102.33 86.72,105.53 86.72,111.23 87.24,111.75 87.24,112.04 87.52,112.32 87.92,112.32 87.92,112.32 88,112.32 v1(88.52,111.8)
GC1: length 36.3
  TOP w0.152: R181.1 88.24,61.62 v1(88.27,61.65) C187.2 89.56,63.7 U23.6
  BOTTOM w0.152: v1(88.27,61.65) 88.27,60.45 87.63,59.82 81.79,59.82 79.25,62.36 79.25,73.66 81.28,75.69 81.28,79.88 80.52,80.65 JP1.2
IN1: length 6.2
  TOP w0.216: U23.22 92.59,67.03 92.59,68.73 C125.1
  TOP w0.305: R207.2 C125.1 R211.2 R210.2 C227.2
IN-1: length 18.9
  TOP w0.152: R290.2 79.86,70.03 T1.6
  TOP w0.191: R199.1 92.33,73.25 92.67,73.59 92.67,74.31 92.36,74.61 91.91,74.61 91.8,74.5 91.8,74.44 91.69,74.33 91.54,74.33 91.43,74.44 91.43,74.5 91.32,74.61 91.17,74.61 91.06,74.5 91.06,74.44 90.95,74.33 90.8,74.33 90.69,74.44 90.69,74.5 90.59,74.61 86.38,74.61 83.57,71.81 82.93,71.81 81.14,70.03 T1.6
  TOP w0.305: C227.1 R210.1 R199.1
IN_1: length 6.1
  TOP w0.152: 77.42,70 T1.1
  TOP w0.305: R290.1 76.23,70 C190.2 C194.1 R297.2
IOUTB1: length 21.9
  TOP w0.102: R42.1 50.34,63.63 50.04,63.63 49.46,64.21 49.39,64.21 47.6,64.21 47.44,64.05 46.91,64.05 46.91,64.05 U1.B34
  TOP w0.152: R42.1 50.91,63.4 51.1,63.59 53.63,63.59 54.58,62.64 54.58,59.51 55.89,58.2 60.79,58.2 61.16,57.84 C204.1
  TOP w0.305: C204.1 C216.2 L1.2
IOUTB2: length 21.9
  TOP w0.102: R99.1 50.37,63.86 50.14,63.86 49.56,64.44 49.33,64.44 47.6,64.44 47.39,64.65 47.23,64.65 47.23,64.64 46.97,64.64 46.97,64.65 46.91,64.65 46.91,64.65 U1.B35
  TOP w0.152: C204.2 61.16,58.85 60.79,58.48 56.01,58.48 54.86,59.63 54.86,62.75 53.75,63.87 51.1,63.87 50.91,64.06 R99.1
  TOP w0.305: C204.2 C219.1 L2.2
IOUTC1: length 21.9
  TOP w0.102: U1.B37 46.91,65.85 46.91,65.85 47.44,65.85 47.6,65.68 49.31,65.68 49.66,66.03 49.72,66.03 50.06,66.37 50.26,66.37 50.49,66.6 R100.1
  TOP w0.152: C185.1 61.16,72.44 60.82,72.1 55.81,72.1 54.61,70.9 54.61,68.07 52.96,66.42 51.09,66.42 50.91,66.6 R100.1
  TOP w0.305: L3.2 C196.2 C185.1
IOUTC2: length 21.9
  TOP w0.102: R101.1 50.52,65.94 50.42,66.04 50.41,66.03 50.05,66.03 49.82,65.8 49.75,65.8 49.41,65.46 47.6,65.46 47.39,65.25 47.23,65.25 47.23,65.25 46.97,65.25 46.97,65.25 46.91,65.25 46.91,65.25 U1.B36
  TOP w0.152: R101.1 50.91,65.94 51.11,66.14 53.17,66.14 53.19,66.17 53.21,66.17 54.89,67.84 54.89,67.86 54.89,70.79 55.93,71.82 60.76,71.82 61.16,71.42 C185.2
  TOP w0.305: L4.2 C191.1 C185.2
IP1: length 6.3
  TOP w0.216: U23.21 92.97,67 92.97,68.63 93.32,68.99 93.34,68.99
  TOP w0.305: R206.1 93.34,68.99 R209.2 R208.2 C214.2
IP-1: length 18.9
  TOP w0.191: T1.4 81.18,73.84 82.86,72.15 83.43,72.15 86.23,74.95 86.52,74.95 92.51,74.95 93.01,74.45 93.01,73.39 93.34,73.05 93.34,73.05
  TOP w0.305: 93.34,73.05 R208.1 C214.1 ; T1.4 R289.2
IP_1: length 6
  TOP w0.305: R296.2 C195.2 C190.1 76.2,73.84 T1.3 R289.1
LMK_SPI_CLK: length 39.4
  L3_PWR w0.152: v1(82.89,102.97) 77.26,108.61 66.19,108.61 64.65,110.15 55.09,110.15 54.85,109.91 52.3,109.91 51.39,110.81 47.59,110.81 47.15,110.37 v2(47.11,110.37)
LMK_SPI_EN: length 39.1
  L3_PWR w0.152: v1(82.89,102.17) 82.89,102.2 76.91,108.18 66.14,108.18 65.14,109.18 63.96,109.18 63.95,109.19 63.55,109.19 63.54,109.18 55.38,109.18 55.02,109.55 51.97,109.55 51.21,110.31 48.62,110.31 48.4,110.53 47.98,110.53 v2(47.47,110.01)
LMK_SPI_MISO: length 37.4
  BOTTOM w0.152: v2(49.59,103.18) 49.62,103.18 50.14,102.67 54.55,102.67 59.79,107.91 76.8,107.91 80.93,103.77 U4.14
LMK_SPI_MOSI: length 55.2
  TOP w0.152: v1(48.89,113.33) 47.32,111.76 47.32,111.25 46.79,110.72 U16.46
  L3_PWR w0.152: v1(82.89,104.57) 87.43,104.57 87.88,105.03 87.88,108.2 84.33,111.76 80.39,111.76 78.61,113.54 69.08,113.54 69.07,113.55 69.07,113.56 68.33,114.3 62.4,114.3 61.51,115.19 49.69,115.19 48.89,114.4 v1(48.89,113.33)
LO_P1: length 2.2
  TOP w0.305: R169.1 C121.2 84.68,65.46 C260.2
LO_P3: length 46.7
  BOTTOM w0.305: v1(83.19,65.94) 82.53,66.59 82.53,71.61 85.85,74.93 90.68,74.93 94.49,78.74 94.61,78.74 96.01,78.74 100.23,82.96 J1.1
LON1: length 3.6
  TOP w0.305: R174.2 C131.2 89.63,64.44 89.89,64.7 U23.4
LOP1: length 3.6
  TOP w0.305: R169.2 C122.2 89.73,65.46 89.99,65.2 U23.3
MOD_PD: length 49.8
  L6_PWR w0.152: v1(87.72,111.84) 87,111.11 87,105.28 85.63,103.92 85.43,103.74 83.92,102.23 83.92,100.27 85.67,98.52 85.67,98.37 86.33,97.71 87.3,97.71 88.24,96.77 88.24,96.16 88.75,95.65 88.75,83.92 88.14,83.31 88.14,70.74 88.67,70.21 88.67,69.4 88.65,69.37 88.65,67.33 v1(89.05,66.93)
  BOTTOM w0.152: U4.27 v1(87.72,111.84)
OSC: length 12.7
  TOP w0.305: C301.2 81.41,125.37 73.03,116.99 SJP5.1
OSC_IN: length 3.1
  TOP w0.152: C60.2 51.59,107.95 51.05,107.95 50.3,107.19 U16.36
OSCIN: length 9.6
  TOP w0.305: C301.1 81.41,129.49 84.51,132.59 J11.1
PARITYN: length 53.2
  TOP w0.127: 43.51,59.38 43.5,59.39 43.5,59.91 43.4,60.01 43.4,60.24 43.38,60.25 43.38,60.58 U1.A29
  TOP w0.152: v1(13.97,48.28) 14.12,48.28 14.48,48.64 24.27,48.64 24.6,48.31 25.26,48.31 25.56,48.61 25.56,49.5 25.7,49.63 25.89,49.63 26.02,49.5 26.02,48.61 26.32,48.31 26.74,48.31 27.03,48.61 27.03,49.5 27.17,49.63 27.36,49.63 27.49,49.5 27.49,48.61 27.79,48.31 28.21,48.31 28.51,48.61 28.51,49.5 28.64,49.63 28.83,49.63 28.97,49.5 28.97,48.61 29.26,48.31 29.68,48.31 29.98,48.61 29.98,49.5 30.12,49.63 30.3,49.63 30.44,49.5 30.44,48.61 30.74,48.31 31.16,48.31 31.45,48.61 31.45,49.5 31.59,49.63 31.78,49.63 31.91,49.5 31.91,48.61 32.21,48.31 32.63,48.31 32.93,48.61 32.93,49.5 33.06,49.63 33.25,49.63 33.38,49.5 33.38,48.61 33.68,48.31 34.1,48.31 34.28,48.13 35.31,48.13 35.89,48.72 35.89,48.97 43.51,56.59 43.51,59.38
  BOTTOM w0.152: v1(13.97,48.28) 13.67,48.58 12.41,48.58 12.3,48.47 J13.172
PARITYP: length 53.4
  TOP w0.127: U1.B26 43.1,60.16 43.13,60.13 43.13,59.9 43.23,59.8 43.23,59.47
  TOP w0.152: v1(13.97,49.16) 14.03,49.16 14.27,48.92 24.38,48.92 24.71,48.59 25.15,48.59 25.28,48.72 25.28,49.61 25.58,49.91 26,49.91 26.3,49.61 26.3,48.72 26.43,48.59 26.62,48.59 26.76,48.72 26.76,49.61 27.05,49.91 27.47,49.91 27.77,49.61 27.77,48.72 27.91,48.59 28.09,48.59 28.23,48.72 28.23,49.61 28.53,49.91 28.95,49.91 29.24,49.61 29.24,48.72 29.38,48.59 29.57,48.59 29.7,48.72 29.7,49.61 30,49.91 30.42,49.91 30.72,49.61 30.72,48.72 30.85,48.59 31.04,48.59 31.18,48.72 31.18,49.61 31.47,49.91 31.89,49.91 32.19,49.61 32.19,48.72 32.33,48.59 32.51,48.59 32.65,48.72 32.65,49.61 32.95,49.91 33.37,49.91 33.66,49.61 33.66,48.72 33.8,48.59 34.22,48.59 34.4,48.41 35.19,48.41 35.61,48.83 35.61,49.09 43.23,56.71 43.23,59.47
  BOTTOM w0.152: v1(13.97,49.16) 13.67,48.86 12.41,48.86 12.3,48.97 J13.170
PD1: length 17.6
  TOP w0.152: v1(90.09,66.42) 90.32,66.2 U23.1
  L6_PWR w0.152: JP5.2 91.95,76.2 89.28,73.53 89.28,70.48 89.81,69.95 89.81,66.7 v1(90.09,66.42)
  BOTTOM w0.152: R185.1 90.07,66.45 v1(90.09,66.42)
PLLAVDD: length 1.2
  BOTTOM w0.254: v5(45.49,68.45) 45.31,68.63 C49.1 ; v5(45.49,68.45) 45.67,68.63 C48.1 ; v5(45.49,68.45) v5(45.49,68.73)
  vias: v1(54.39,76.96)
PRI_DAC_CLKN: length 62.9
  L3_PWR w0.122: v1(53.43,101.58) 53.43,101.27 54.51,100.19 54.51,98.15 38.75,82.4 9.51,82.4 8.85,83.06 7.16,83.06 7.01,82.91 7.01,82.53 7.08,82.46 v1(7.35,82.46)
  BOTTOM w0.152: J13.63 6.13,80.48 6.24,80.6 6.52,80.6 6.82,80.9 7.04,80.9 7.54,81.4 7.54,81.85 7.35,82.04 v1(7.35,82.46)
PRI_DAC_CLKP: length 62.8
  L3_PWR w0.122: v1(6.73,81.84) 6.73,82.32 6.5,82.55 6.5,82.88 6.96,83.34 8.97,83.34 9.63,82.68 38.64,82.68 54.23,98.27 54.23,100.08 53.21,101.09 52.89,101.09 v1(52.67,100.87)
  BOTTOM w0.152: v1(6.73,81.84) 7.16,81.84 7.26,81.73 7.26,81.51 6.93,81.18 6.71,81.18 6.4,80.87 6.24,80.87 6.13,80.99 J13.61
PWR_IN:
  vias: v1(14.1,100.84) v1(14.1,100.2) v1(14.1,99.57) v1(14.1,97.79) v1(14.1,97.16) v1(14.73,100.84) v1(14.73,100.2) v1(14.73,99.57) v1(14.73,97.79) v1(14.73,97.16) v1(99.69,5.84) v1(99.69,5.21) v1(99.69,4.57) v1(100.46,5.84) v1(100.46,5.21) v1(100.46,4.57) v1(101.22,5.84) v1(101.22,5.21) v1(101.22,4.57) v1(101.47,16.26) v1(102.11,16.26) v1(102.87,16.26) v1(102.87,15.62) v1(102.87,14.99)
QN1: length 6.4
  TOP w0.216: C126.1 92.2,60.76 92.57,61.12 92.57,62.88 U23.9
  TOP w0.305: C229.2 R214.2 R215.2 C126.1 R225.2
QN-1: length 18.9
  TOP w0.191: R201.1 92.2,56.65 92.54,56.31 92.54,55.53 92.2,55.2 91.78,55.2 91.67,55.3 91.67,55.36 91.56,55.47 91.41,55.47 91.3,55.36 91.3,55.3 91.19,55.2 91.04,55.2 90.93,55.3 90.93,55.36 90.83,55.47 90.67,55.47 90.57,55.36 90.57,55.3 90.46,55.2 88.95,55.2 85.62,58.52 85.34,58.52 85.34,58.52 82.88,58.52
  TOP w0.216: 82.88,58.52 81.15,60.25 T2.4
  TOP w0.305: T2.4 R292.2 ; R201.1 R214.1 C229.1
QN_1: length 6
  TOP w0.305: R303.2 C218.1 C222.2 76.2,60.25 T2.3 R292.1
QP1: length 6.4
  TOP w0.216: C126.2 93.22,60.76 92.95,61.03 92.95,62.87 U23.10
  TOP w0.305: C126.2 R213.2 R212.2 C228.2
  TOP w0.495: R226.1 C126.2
QP-1: length 18.9
  TOP w0.191: 82.84,58.18 85.48,58.18 88.81,54.85 92.34,54.85 92.88,55.39 92.88,56.3 93.22,56.63 R200.1
  TOP w0.216: 82.84,58.18 81.1,56.44 T2.6
  TOP w0.305: T2.6 R291.2 ; R200.1 R212.1 C228.1
QP_1: length 6
  TOP w0.305: R291.1 T2.1 76.2,56.44 C222.1 C199.2 R302.2
REFIN: length 15.6
  TOP w0.305: R48.1 58.98,116.38 58.98,115.37 53.33,109.72 C60.1
REFINN: length 3.1
  TOP w0.305: U26.5 64.86,123.28 R48.2
REFOUT: length 6.5
  TOP w0.305: U26.7 67.95,121.98 69.22,123.24 R49.2
REFOUT1: length 9.2
  TOP w0.305: R49.1 69.22,129.64 72.16,132.59 J6.1
REFOUT3: length 3.6
  TOP w0.305: R53.2 69.04,119.41 67.12,121.33 U26.8
RF1: length 13.2
  TOP w0.305: R165.2 C157.2 R167.1
RF-1: length 1.1
  TOP w0.305: C258.1 95.89,65.2 U23.16
RF_1: length 2
  TOP w0.305: C258.2 C156.2 R167.2
RF_OUT1: length 1
  BOTTOM w0.305: v1(95.91,64.16) R103.1
RF_OUT_1: length 1
  BOTTOM w0.305: R94.2 114.17,64.13 v1(114.15,64.16)
RFOUT1: length 4.4
  TOP w0.305: R165.1 J7.1
ROUT: length 2.5
  BOTTOM w0.305: C257.2 96.44,60.86 R137.2 95.91,61.38 R103.2
ROUT1: length 2
  BOTTOM w0.305: C257.1 98.12,59.18 U8.1
ROUT2: length 2.6
  BOTTOM w0.305: U8.3 L5.2 C249.2
ROUT3: length 1.5
  BOTTOM w0.305: U7.7 106.3,59.19 C249.1
ROUT4: length 4.3
  BOTTOM w0.305: R94.1 R93.2 114.17,59.69 113.66,59.18 113.16,59.18 113.15,59.19 U7.18
SPI_CLK: length 156.8
  TOP w0.102: 44.6,60.43 v5(44.6,60.22)
  TOP w0.127: U1.A31 44.6,60.43
  TOP w0.152: v1(88.94,98.72) 87.29,98.72 85.66,100.36 85.66,100.74 86.51,101.59 86.51,104.55 v1(91.92,109.96)
  L6_PWR w0.152: v1(88.94,98.72) 96.8,98.72 112.5,83.03 112.5,76.38 112.4,76.28 112.4,76.28 111.8,75.68 111.8,61.78 112.27,61.32 112.27,60.2 112.01,59.95 112.01,57.15 112.2,57.01 112.2,56.54 112.56,56.18 v2(112.56,56.17)
  BOTTOM w0.102: 46.36,59.23 46.36,60.2 45.64,60.92 45.36,60.92 45.35,60.93 45.06,60.93 44.87,60.73 44.87,60.64 44.6,60.37 v5(44.6,60.22)
  BOTTOM w0.152: v1(88.94,98.72) 88.66,98.45 87.65,98.45 67.44,78.23 57.15,78.23 56.77,77.85 56.77,72.01 54.99,70.23 54.99,67.95 53.98,66.93 53.98,59.18 53.09,58.29 46.86,58.29 46.36,58.8 46.36,59.23 ; v1(91.92,109.96) 92.52,110.55 U4.33 92.52,113.32 93.04,113.84 93.04,116.33 92.74,116.64 92.08,116.64 91.19,115.75 v1(91.19,115.15)
SPI_DATA: length 151
  TOP w0.102: 44.09,60.17 v5(44.2,60.07)
  TOP w0.127: U1.A30 44,60.3
  TOP w0.152: v1(84.91,98.2) 85.06,98.35 85.06,101.24 85.32,101.5 85.32,104.34 90.91,109.93 90.91,111.78 v1(90.92,111.8) ; 44.09,60.17 44,60.27 44,60.3
  L6_PWR w0.152: v1(90.92,111.8) 92.35,110.36 93.34,110.36 96.65,107.06 96.65,100.15 113.54,83.26 113.54,63.76 114.05,63.25 114.05,57.25 113.8,57.01 113.8,56.99 113.52,56.7 113.22,56.7 112.91,56.4 112.91,56.02 112.7,55.82 112.58,55.82 112.31,55.54 v2(111.91,55.54)
  BOTTOM w0.102: 48.46,61.87 48.18,61.59 45.11,61.59 44.44,60.92 44.44,60.71 44.2,60.47 v5(44.2,60.07)
  BOTTOM w0.152: U5.5 92.46,114.55 90.93,113.03 90.93,111.81 v1(90.92,111.8) ; 48.46,61.87 48.67,62.08 48.67,62.26 49.56,63.14 49.56,63.14 49.68,63.26 49.68,63.27 54.48,68.07 54.48,70.23 56.39,72.14 56.39,78.11 57.02,78.74 66.8,78.74 74.27,86.21 74.27,86.21 84.91,96.85 v1(84.91,98.2)
SYNC: length 11.6
  TOP w0.216: 40.81,102.65 41.33,103.18 U16.6
  TOP w0.495: 40.81,102.65 36.02,97.87 36.02,95.99 J10.1
SYNCN: length 59.2
  TOP w0.127: U1.B5 43.1,68.55 43.1,69.68 43.09,69.69 43.09,69.72
  TOP w0.152: 43.09,69.72 43.09,72.5 42.82,72.77 v2(42.42,72.77) ; v1(26.42,46.31) 26.11,46.61 24.89,46.61 24.03,47.47 11.26,47.47 10.9,47.12 8.38,47.12 8,46.74 R177.2
  BOTTOM w0.152: v2(42.42,72.77) 42.29,72.9 40.51,72.9 27.81,60.2 27.81,46.86 27.56,46.61 26.72,46.61 v1(26.42,46.31)
SYNCP: length 59.2
  TOP w0.127: U1.A5 43.36,69.24 43.36,69.59 43.37,69.61 43.37,69.72
  TOP w0.152: v1(26.42,47.19) 26.11,46.89 25.01,46.89 24.14,47.75 11.14,47.75 10.78,47.4 8.37,47.4 8.01,47.75 R175.2 ; 43.37,69.72 43.37,72.62 42.76,73.23 42.19,73.23 v2(42.06,73.36)
  BOTTOM w0.152: v2(42.06,73.36) 41.88,73.18 40.4,73.18 27.53,60.31 27.53,46.98 27.44,46.89 26.72,46.89 v1(26.42,47.19)
